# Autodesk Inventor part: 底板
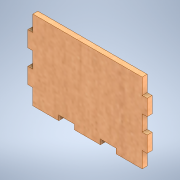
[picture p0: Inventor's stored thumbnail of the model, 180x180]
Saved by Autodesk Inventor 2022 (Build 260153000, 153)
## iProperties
Created: 2024-11
Part Number: 底板
Material: MDF 中密度繊維ボード
Document SubType Name: Modeling
Designer: shimizu
Density: 0.8 g/cm^3
Appearance: サクラ材 - ナチュラル 抑えた光沢
Author: shimizu
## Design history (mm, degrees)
sketch "スケッチ1"
  geometry: L1 (-25.119, 10.226)-(29.881, 10.226); L2 (29.881, -29.774)-(-25.119, -29.774); L3 (-25.119, 2.226)-(-27.619, 2.226); L4 (-27.619, 2.226)-(-27.619, -5.774); L5 (-27.619, -5.774)-(-25.119, -5.774); L6 (-25.119, -13.774)-(-27.619, -13.774); L7 (-27.619, -13.774)-(-27.619, -21.774); L8 (-27.619, -21.774)-(-25.119, -21.774); L9 (29.881, 2.226)-(32.381, 2.226); L10 (32.381, 2.226)-(32.381, -5.774); L11 (32.381, -5.774)-(29.881, -5.774); L12 (29.881, -13.774)-(32.381, -13.774); L13 (32.381, -13.774)-(32.381, -21.774); L14 (32.381, -21.774)-(29.881, -21.774); L15 (-25.119, 2.226)-(-25.119, 10.226); L16 (-25.119, -29.774)-(-25.119, -21.774); L17 (-25.119, -13.774)-(-25.119, -5.774); L18 (29.881, 10.226)-(29.881, 2.226); L19 (29.881, -5.774)-(29.881, -13.774); L20 (29.881, -21.774)-(29.881, -29.774); L21 (-12.119, -29.774)-(-4.119, -29.774); L22 (-4.119, -29.774)-(-4.119, -27.274); L23 (-4.119, -27.274)-(-12.119, -27.274); L24 (-12.119, -27.274)-(-12.119, -29.774); L25 (8.881, -29.774)-(16.881, -29.774); L26 (16.881, -29.774)-(16.881, -27.274); L27 (16.881, -27.274)-(8.881, -27.274); L28 (8.881, -27.274)-(8.881, -29.774); 3 further points
  constraints: 56 end point, 18 parallel, 9 perpendicular, 7 horizontal, 2 point on line
  dimensions: "d16" = 60 distance between parallel lines of L13 L7; "d17" = 8 distance between parallel lines of L22 L24; "d18" = 8 distance between parallel lines of L26 L28; "d19" = 2.5 distance of L23.end L21.start; "d20" = 2.5 distance of L25.end L26.end; "d21" = 13 distance between parallel lines of L16 L24; "d22" = 13 distance between parallel lines of L28 L22; "d23" = 13 distance between parallel lines of L20 L26
extrude "押し出し1" new body sketch "スケッチ1" distance "d2" = 2.5; taper "d3" = 0 deg
node "ソリッド1"
